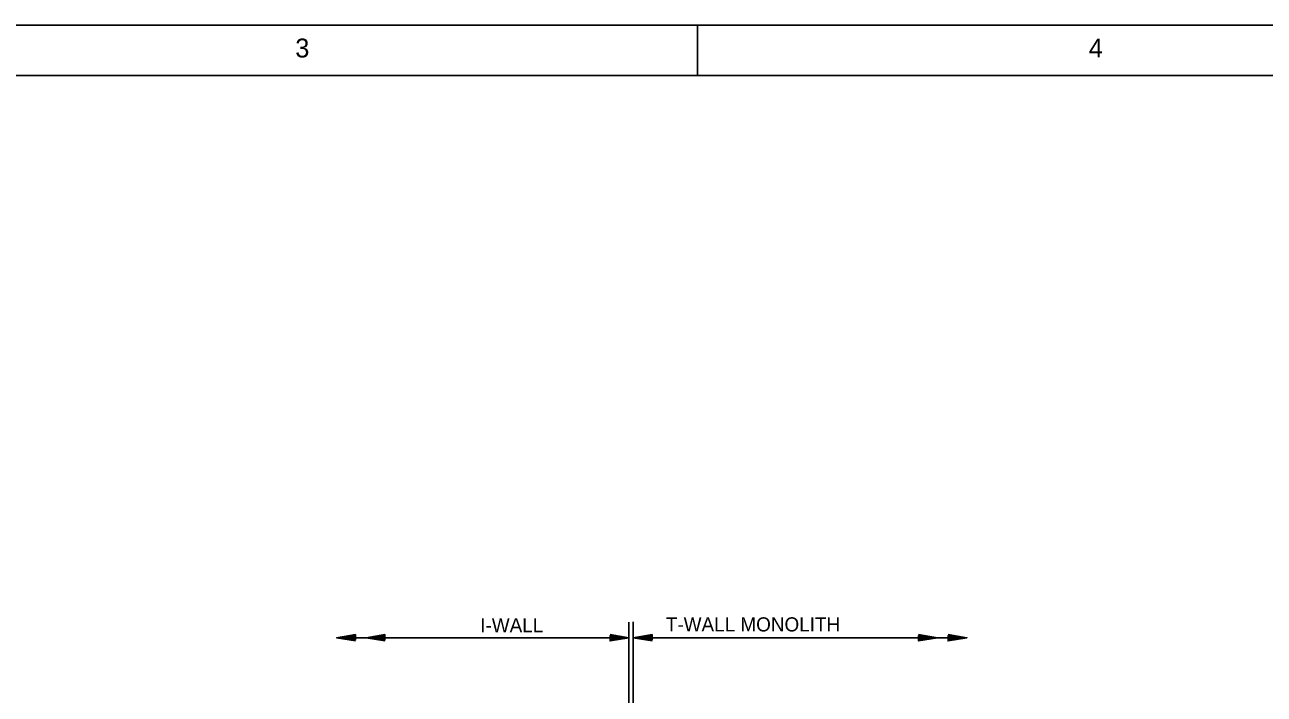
# Model space of a CAD drawing. Extents: x 22369.6 to 22428.3, y 22369.6 to 22415.
# Drawn here: x 22394.12 to 22410.49, y 22406.12 to 22414.96 of the extents above; entities that cross this region are included whole.
import ezdxf

# ---------------------------------------------------------------- set-up
doc = ezdxf.new("R2010")
doc.units = 0
for name, color, linetype in [('Level 1', 7, 'Continuous'), ('Level 10', 7, 'Continuous'), ('Level 2', 7, 'Continuous'), ('Level 4', 7, 'Continuous'), ('Level 9', 7, 'Continuous')]:
    doc.layers.add(name, color=color, linetype=linetype)

msp = doc.modelspace()

# ---------------------------------------------------------------- linework, layer by layer
at = {"layer": 'Level 1'}
for p, q in [((22402.103, 22402.309), (22402.103, 22407.07)), ((22402.159, 22402.311), (22402.159, 22407.074)), ((22402.103, 22406.864), (22398.241, 22406.864)), ((22402.159, 22406.864), (22406.567, 22406.864))]:
    msp.add_line(p, q, dxfattribs=at)
msp.add_lwpolyline([(22369.621, 22414.955), (22428.288, 22414.955), (22428.288, 22369.621), (22369.621, 22369.621)], close=True, dxfattribs=at)
at = {"layer": 'Level 10'}
msp.add_line((22403.008, 22414.288), (22403.008, 22414.96), dxfattribs=at)
at = {"layer": 'Level 2'}
for p, q in [((22398.241, 22406.864), (22398.241, 22406.864)), ((22398.31, 22406.864), (22398.31, 22406.864)), ((22398.835, 22406.864), (22398.835, 22406.864)), ((22398.858, 22406.878), (22398.858, 22406.878)), ((22398.858, 22406.86), (22398.858, 22406.86)), ((22398.869, 22406.892), (22398.869, 22406.892)), ((22398.879, 22406.905), (22398.879, 22406.905)), ((22402.034, 22406.864), (22402.034, 22406.864)), ((22402.103, 22406.864), (22402.103, 22406.864)), ((22402.159, 22406.864), (22402.159, 22406.864)), ((22402.228, 22406.864), (22402.228, 22406.864)), ((22405.928, 22406.905), (22405.928, 22406.905)), ((22405.928, 22406.893), (22405.928, 22406.893)), ((22405.939, 22406.881), (22405.939, 22406.881)), ((22405.95, 22406.868), (22405.95, 22406.868)), ((22405.95, 22406.849), (22405.95, 22406.849)), ((22405.972, 22406.864), (22405.972, 22406.864)), ((22406.498, 22406.864), (22406.498, 22406.864)), ((22406.567, 22406.864), (22406.567, 22406.864)), ((22398.869, 22406.846), (22398.869, 22406.846)), ((22398.879, 22406.834), (22398.879, 22406.834)), ((22398.879, 22406.822), (22398.879, 22406.822)), ((22405.928, 22406.822), (22405.928, 22406.822)), ((22405.939, 22406.836), (22405.939, 22406.836))]:
    msp.add_line(p, q, dxfattribs=at)
for points in [[(22398.49, 22406.822), (22398.241, 22406.864), (22398.49, 22406.905), (22398.49, 22406.834), (22398.31, 22406.864), (22398.479, 22406.892), (22398.479, 22406.846), (22398.377, 22406.864), (22398.469, 22406.878), (22398.469, 22406.86), (22398.446, 22406.864)], [(22398.879, 22406.822), (22398.63, 22406.864), (22398.879, 22406.905), (22398.879, 22406.834), (22398.699, 22406.864), (22398.869, 22406.892), (22398.869, 22406.846), (22398.766, 22406.864), (22398.858, 22406.878), (22398.858, 22406.86), (22398.835, 22406.864)], [(22401.854, 22406.905), (22402.103, 22406.864), (22401.854, 22406.822), (22401.854, 22406.893), (22402.034, 22406.864), (22401.864, 22406.836), (22401.864, 22406.881), (22401.967, 22406.864), (22401.875, 22406.849), (22401.875, 22406.868), (22401.898, 22406.864)], [(22402.408, 22406.822), (22402.159, 22406.864), (22402.408, 22406.905), (22402.408, 22406.834), (22402.228, 22406.864), (22402.397, 22406.892), (22402.397, 22406.846), (22402.295, 22406.864), (22402.387, 22406.878), (22402.387, 22406.86), (22402.364, 22406.864)], [(22405.928, 22406.905), (22406.178, 22406.864), (22405.928, 22406.822), (22405.928, 22406.893), (22406.108, 22406.864), (22405.939, 22406.836), (22405.939, 22406.881), (22406.042, 22406.864), (22405.95, 22406.849), (22405.95, 22406.868), (22405.972, 22406.864)], [(22406.318, 22406.905), (22406.567, 22406.864), (22406.318, 22406.822), (22406.318, 22406.893), (22406.498, 22406.864), (22406.328, 22406.836), (22406.328, 22406.881), (22406.431, 22406.864), (22406.339, 22406.849), (22406.339, 22406.868), (22406.362, 22406.864)]]:
    msp.add_lwpolyline(points, dxfattribs=at)
at = {"layer": 'Level 9'}
msp.add_line((22371.621, 22414.288), (22423.952, 22414.288), dxfattribs=at)

# ---------------------------------------------------------------- texts
at = {"layer": 'Level 1'}
for s, p in [('3', (22397.696, 22414.528)), ('4', (22408.176, 22414.528))]:
    msp.add_text(s, height=0.25, dxfattribs=at).set_placement(p)
at = {"layer": 'Level 4'}
for s, height, p in [('I-WALL', 0.1867, (22400.139, 22406.935)), ('T-WALL MONOLITH', 0.18667, (22402.59, 22406.947))]:
    msp.add_text(s, height=height, dxfattribs=at).set_placement(p)

doc.saveas('drawing.dxf')
